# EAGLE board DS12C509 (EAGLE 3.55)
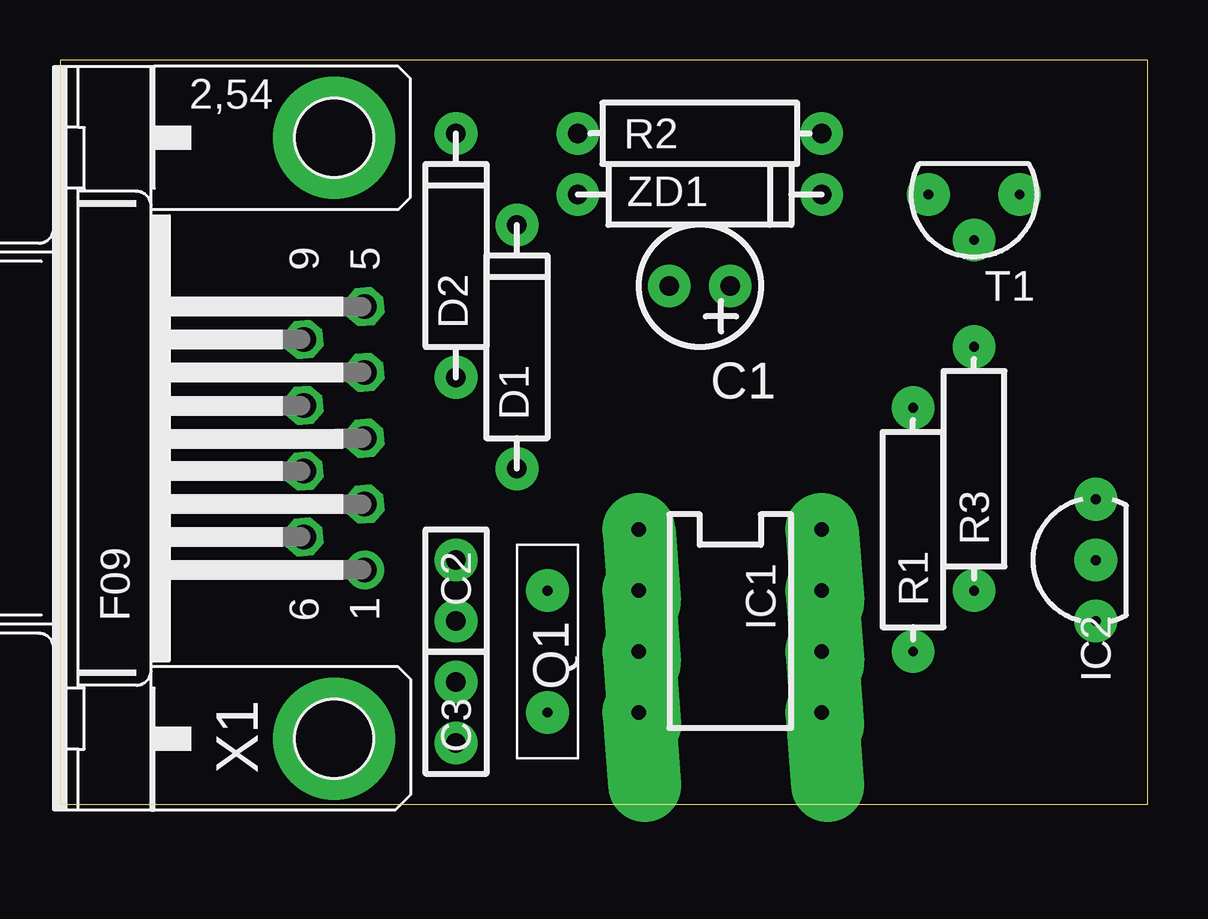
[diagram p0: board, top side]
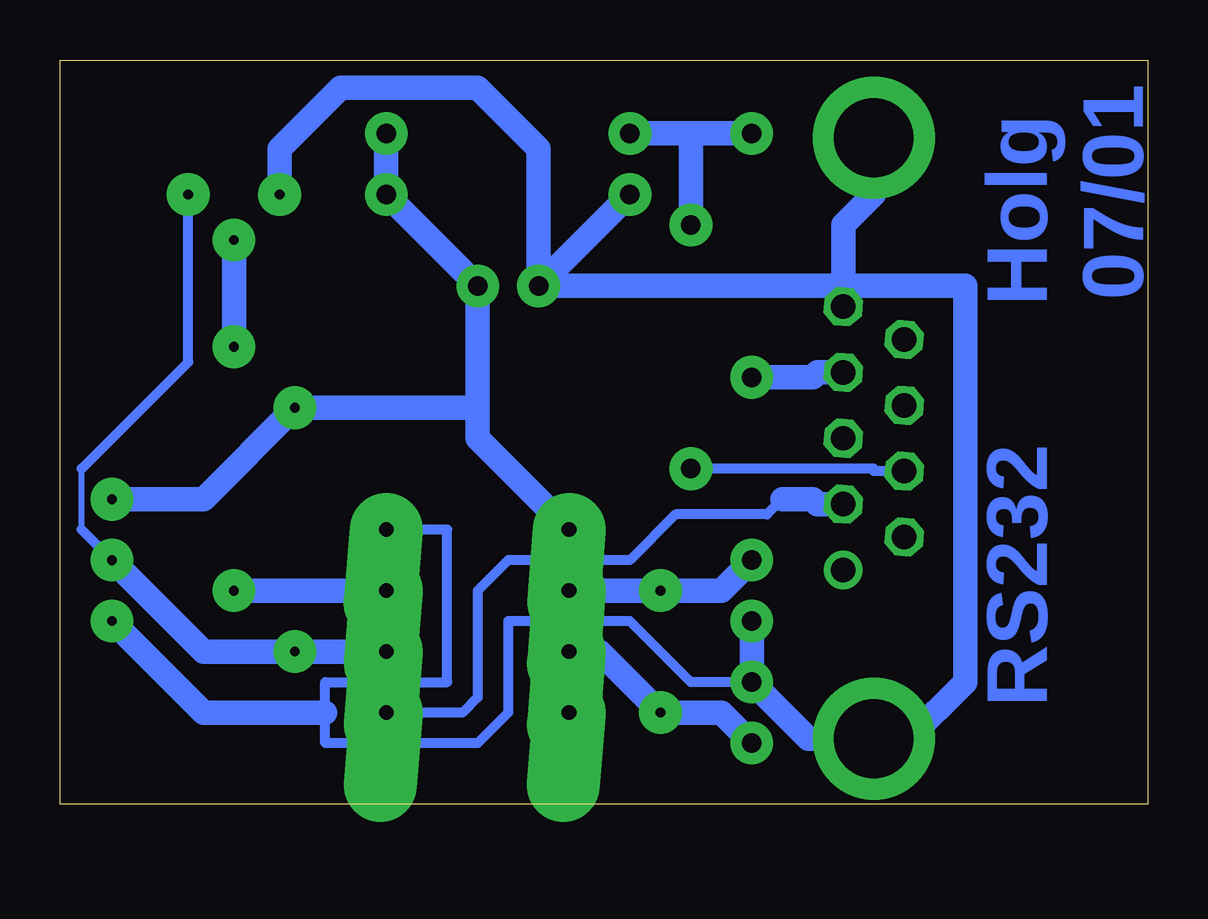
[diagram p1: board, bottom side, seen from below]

Size 45.35 x 31 mm. Coordinates in mm from the lower left corner, seen from the top.
Outline: 0,0 45.35,0 45.35,31 0,31 0,0
Copper layers used: Bottom

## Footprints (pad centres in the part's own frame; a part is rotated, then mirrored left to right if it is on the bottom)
KO01 = drill 0.813 pad 1.778 round:  0,0;  2.54,0
RM2,5 = drill 0.813 pad 1.778 round:  0,0;  2.54,0
O04 = drill 0.813 pad 1.778 round:  0,0;  10.16,0
L-8B = drill 0.61 pad 3.048 offset:  0,0;  2.54,0;  5.08,0;  7.62,0;  7.62,7.62;  5.08,7.62;  2.54,7.62;  0,7.62
92-B = drill 0.406 pad 1.778 round:  -2.54,0;  2.54,0;  0,0
ARZ_ST = drill 0.406 pad 1.778 round:  0,0;  5.08,0
S04 = drill 0.406 pad 1.778 round:  0,0;  10.16,0
S04' = drill 0.813 pad 1.778 round:  0,0;  10.16,0
92 = drill 0.406 pad 1.778 round:  -0.635,0;  1.27,1.905;  3.175,0
9HP = drill 1.016 pad 1.6 round:  -5.486,-1.27 | drill 1.016 pad 1.6 octagon:  -2.743,-1.27;  0,-1.27;  2.743,-1.27;  5.486,-1.27;  -4.115,1.27;  -1.372,1.27;  1.372,1.27;  4.115,1.27 | drill 3.302 pad 5.08 round:  -12.522,0;  12.522,0

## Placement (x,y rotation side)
C1  47u  [KO01]  27.94,21.59 180 top
C2  22p  [RM2,5]  16.51,7.62 90 top
C3  22p  [RM2,5]  16.51,5.08 270 top
D1  1N4148  [O04]  19.05,13.97 90 top
D2  1N4148  [O04]  16.51,17.78 90 top
IC1  12C509P  [L-8B]  24.13,11.43 270 top
IC2  DS1821  [92-B]  43.18,10.16 90 top
Q1  4MHz  [ARZ_ST]  20.32,8.89 270 top
R1  4k7  [S04]  35.56,6.35 90 top
R2  1k  [S04']  21.59,27.94 0 top
R3  10k  [S04]  38.1,8.89 90 top
T1  BC546  [92]  39.37,25.4 180 top
X1  F09HP  [9HP]  11.43,15.24 90 top
ZD1  5V1  [O04]  21.59,25.4 0 top

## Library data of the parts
C1-C3 D1 D2 R2 ZD1 = holgeins
IC1 IC2 Q1 R1 R3 T1 = holg_plt
X1 = subd-a

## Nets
+5V: C1. IC1. IC2. R1. R2. ZD1.
GND: C1. C2. C3. IC1. IC2. T1. X1. ZD1.
N$1: IC1. IC2. R1. T1.
N$3: D2. X1.
N$4: D1. X1.
N$6: D1. D2. R2.
N$7: R3. T1.
N$8: C3. IC1. Q1.
N$9: C2. IC1. Q1.
N$10: IC1. R3.
RXD: IC1. X1.

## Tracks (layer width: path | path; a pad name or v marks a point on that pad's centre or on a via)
+5V
  Bottom 1.016: 43.18,12.7 39.37,12.7 R1. 27.94,16.51 | R2. ZD1. 27.94,21.59 27.94,16.51 | 27.94,16.51 27.94,15.24 24.13,11.43
GND
  Bottom 0.406: 12.7,21.59 12.7,20.73 | 9.98,2.72 11.43,2.72 | 11.43,25.4 X1. | C1. 21.59,25.4 | IC1. 29.21,11.43 29.21,5.08 34.29,5.08 34.29,3.81 34.29,2.54 27.94,2.54 26.67,3.81 26.67,7.62 21.59,7.62 19.05,5.08 16.51,5.08
  Bottom 1.016: C1. 21.59,25.4 | 16.51,7.62 16.51,5.08 14.15,2.72 11.43,2.72 | 12.7,21.59 7.62,21.59 7.62,5.08 9.98,2.72 | 11.43,25.4 12.7,24.13 12.7,21.59 | 12.7,21.59 C1. | 43.18,7.62 39.37,3.81 34.29,3.81 | T1. 36.2,27.3 33.66,29.84 27.94,29.84 25.4,27.3 C1.
N$1
  Bottom 0.254: 44.45,11.43 44.45,13.97
  Bottom 0.406: IC2. 44.45,11.43 | 40.01,25.4 40.01,18.41 44.45,13.97
  Bottom 1.016: 31.75,6.35 35.56,6.35 39.37,6.35 IC2.
N$3
  Bottom 1.016: 12.7,17.98 13.77,17.98 13.97,17.78 16.51,17.78
N$4
  Bottom 0.406: 19.05,13.97 11.43,13.97 11.43,13.87 10.16,13.87
N$6
  Bottom 1.016: 19.05,27.94 21.59,27.94 | 19.05,27.94 D2. | D1. 19.05,27.94
N$7
  Bottom 1.016: R3. 38.1,23.5
N$8
  Bottom 1.016: C3. 17.78,3.81 Q1. 22.86,6.35 24.13,6.35
N$9
  Bottom 1.016: 24.13,8.89 20.32,8.89 17.78,8.89 C2.
N$10
  Bottom 1.016: 31.75,8.89 38.1,8.89
RXD
  Bottom 0.406: 31.75,3.81 28.57,3.81 27.94,4.45 27.94,8.89 26.67,10.16 21.59,10.16 19.68,12.06 15.88,12.06 15.24,12.7
  Bottom 1.016: 12.7,12.5 13.77,12.5 13.97,12.7 15.24,12.7

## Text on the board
Bottom: 07/01 | Holg | RS232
